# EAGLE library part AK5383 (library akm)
Audio ADC 192kHz, 24-Bit, 2ch, Delta Sigma
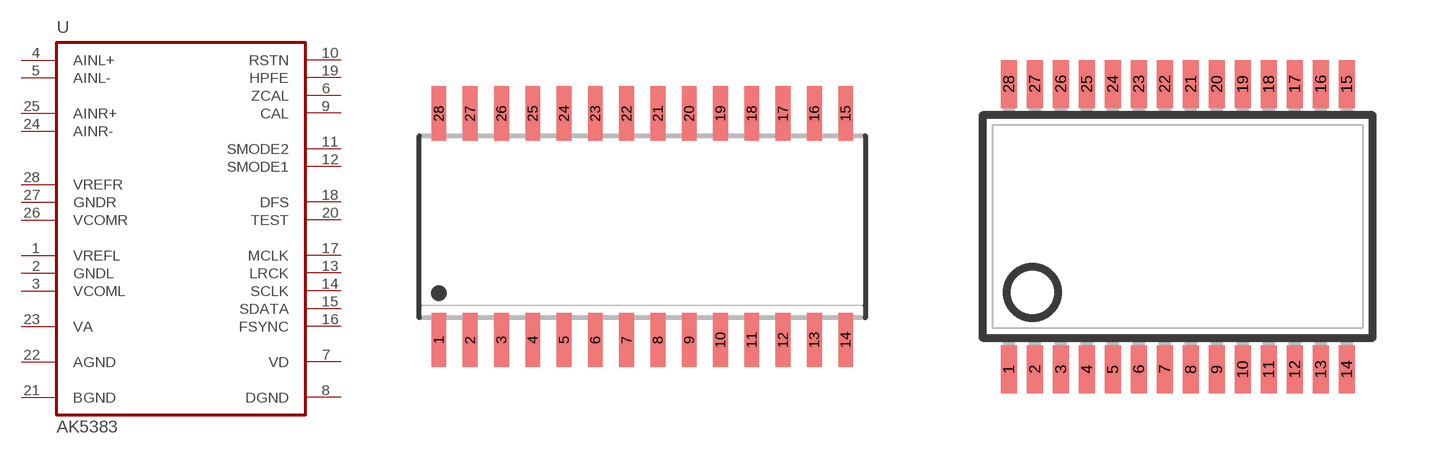
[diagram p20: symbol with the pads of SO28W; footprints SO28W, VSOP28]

Designator prefix U

## AK5383VS  [SO28W]
1  VREFL  out
2  GNDL  pas
3  VCOML  out
4  AINL+  in
5  AINL-  in
6  ZCAL  in
7  VD  pwr
8  DGND  pwr
9  CAL  out
10  RSTN  in
11  SMODE2  in
12  SMODE1  in
13  LRCK
14  SCLK
15  SDATA  out
16  FSYNC
17  MCLK  in
18  DFS  in
19  HPFE  in
20  TEST  in
21  BGND  pwr
22  AGND  pwr
23  VA  pwr
24  AINR-  in
25  AINR+  in
26  VCOMR  out
27  GNDR  pas
28  VREFR  out

## AK5383VF  [VSOP28]
Pads as for SO28W

## Footprint SO28W (pad centres in mm)
SMALL OUTLINE INTEGRATED CIRCUIT wide body 7.5 mm/JEDEC MO-119AB
smd 0.6 x 2.2: 1 -8.255,-4.6; 2 -6.985,-4.6; 3 -5.715,-4.6; 4 -4.445,-4.6; 5 -3.175,-4.6; 6 -1.905,-4.6; 7 -0.635,-4.6; 8 0.635,-4.6; 9 1.905,-4.6; 10 3.175,-4.6; 11 4.445,-4.6; 12 5.715,-4.6; 13 6.985,-4.6; 14 8.255,-4.6; 15 8.255,4.6; 16 6.985,4.6; 17 5.715,4.6; 18 4.445,4.6; 19 3.175,4.6; 20 1.905,4.6; 21 0.635,4.6; 22 -0.635,4.6; 23 -1.905,4.6; 24 -3.175,4.6; 25 -4.445,4.6; 26 -5.715,4.6; 27 -6.985,4.6; 28 -8.255,4.6

## Footprint VSOP28 (pad centres in mm)
VSOP28 9.8 x 5.6 mm, pitch .65 mm
smd 0.4 x 1.2: 1 -4.225,-3.57; 2 -3.575,-3.57; 3 -2.925,-3.57; 4 -2.275,-3.57; 5 -1.625,-3.57; 6 -0.975,-3.57; 7 -0.325,-3.57; 8 0.325,-3.57; 9 0.975,-3.57; 10 1.625,-3.57; 11 2.275,-3.57; 12 2.925,-3.57; 13 3.575,-3.57; 14 4.225,-3.57; 15 4.225,3.57; 16 3.575,3.57; 17 2.925,3.57; 18 2.275,3.57; 19 1.625,3.57; 20 0.975,3.57; 21 0.325,3.57; 22 -0.325,3.57; 23 -0.975,3.57; 24 -1.625,3.57; 25 -2.275,3.57; 26 -2.925,3.57; 27 -3.575,3.57; 28 -4.225,3.57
